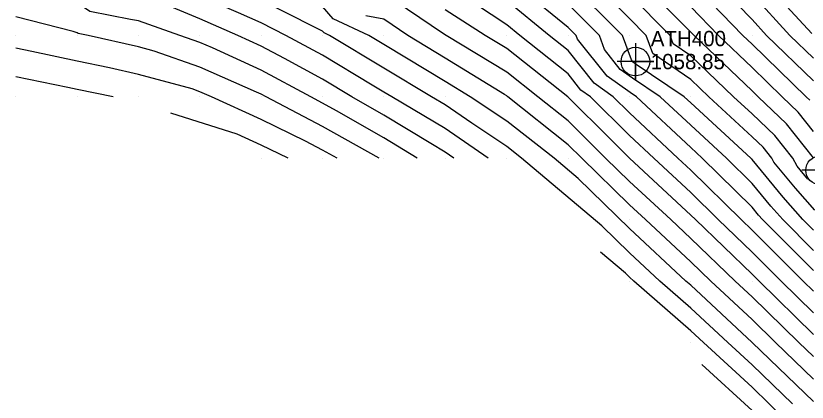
# Model space of a CAD drawing. Extents: x 1213164 to 1213550, y 766120 to 766870.
# Drawn here: x 1213170 to 1213299, y 766240.3 to 766303.2 of the extents above; entities that cross this region are included whole.
import ezdxf

# ---------------------------------------------------------------- set-up
doc = ezdxf.new("R2010")
doc.units = 0
for name, color, linetype in [('Default', 7, 'Continuous'), ('Exist DTM QL2 LIDAR Elevation Point', 7, 'Continuous'), ('Exist DTM Regular Point CELL', 7, 'Continuous'), ('Exist DTM Regular Point Cogo Elevation', 7, 'Continuous'), ('Exist DTM Regular Point Cogo Number', 7, 'Continuous')]:
    doc.layers.add(name, color=color, linetype=linetype)

msp = doc.modelspace()

# ---------------------------------------------------------------- linework, layer by layer
at = {"layer": 'Default'}
for points in [[(1213246.98, 766280), (1213240, 766284.82), (1213231.27, 766290), (1213230, 766290.76), (1213228.08, 766291.92), (1213220, 766296.78), (1213214.03, 766300), (1213210, 766302.06), (1213206.31, 766303.69), (1213200, 766306.44), (1213191.38, 766310), (1213190, 766310.57), (1213185.81, 766311.07), (1213184.05, 766311.81), (1213180, 766314.05), (1213174.54, 766315.46), (1213170, 766316.63)], [(1213241.4, 766280), (1213240, 766280.97), (1213237.62, 766282.38), (1213230, 766287.01), (1213224.78, 766290), (1213220, 766292.88), (1213213.77, 766296.23), (1213210, 766298.26), (1213206.17, 766300), (1213200, 766302.69), (1213195.42, 766304.58), (1213190, 766306.51), (1213186.46, 766307), (1213184, 766307.5), (1213180.32, 766309.98), (1213180, 766310.15), (1213179.79, 766310.21), (1213170, 766312.74)], [(1213300.21, 766271.55), (1213297.07, 766275.13), (1213293.55, 766279.37), (1213293.22, 766280), (1213291.8, 766281.8), (1213290, 766283.51), (1213282.95, 766290), (1213280, 766292.81), (1213273.8, 766297.08), (1213272.75, 766300), (1213270, 766302.77), (1213262.74, 766310)], [(1213300, 766280.07), (1213295.61, 766285.61), (1213291, 766290), (1213290, 766290.97), (1213280.53, 766300), (1213280, 766300.55), (1213270.63, 766310)], [(1213300, 766292.58), (1213292.36, 766300), (1213290, 766302.59), (1213282.84, 766310)], [(1213299.71, 766300.29), (1213290.8, 766310)], [(1213235.43, 766280), (1213230, 766283.3), (1213222.29, 766287.71), (1213220, 766288.99), (1213218.07, 766290), (1213210, 766294.34), (1213202.04, 766297.96), (1213200, 766298.86), (1213196.73, 766300), (1213190, 766302.4), (1213188.69, 766302.58), (1213182.08, 766303.91), (1213180, 766305.32), (1213172.13, 766307.87), (1213170, 766308.4)], [(1213300, 766268.28), (1213298.28, 766270), (1213295.06, 766273.67), (1213290, 766279.77), (1213289.77, 766280), (1213280, 766289.02), (1213278.95, 766290), (1213270.92, 766295.39), (1213270.66, 766295.58), (1213270.32, 766296), (1213268.89, 766300), (1213260, 766308.85)], [(1213299.43, 766289.43), (1213298.82, 766290), (1213290, 766298.56), (1213288.49, 766300), (1213280, 766308.77)], [(1213300, 766261.72), (1213291.7, 766270), (1213291.04, 766270.75), (1213290, 766272.01), (1213281.87, 766280), (1213280, 766281.73), (1213271.13, 766290), (1213270.12, 766290.68), (1213266.38, 766293.34), (1213261.53, 766299.41), (1213261.32, 766300), (1213260, 766301.31), (1213252.81, 766307.19)], [(1213300, 766247.71), (1213297.62, 766250), (1213290, 766257.45), (1213287.26, 766260), (1213280, 766266.94), (1213276.73, 766270), (1213270, 766276.23), (1213266.13, 766280), (1213260, 766286.08), (1213255.06, 766290), (1213250, 766294.02), (1213240.14, 766300), (1213240, 766300.09), (1213239.72, 766300.28), (1213230, 766306.89)], [(1213299.08, 766276.58), (1213297.32, 766278.7), (1213296.63, 766280), (1213293.7, 766283.7), (1213290, 766287.23), (1213286.99, 766290), (1213280, 766296.66), (1213277.12, 766298.64), (1213276.63, 766300), (1213270, 766306.69)], [(1213300, 766296.28), (1213296.17, 766300), (1213290, 766306.77)], [(1213296.59, 766240), (1213290, 766246.35), (1213286.02, 766250), (1213280, 766255.61), (1213274.96, 766260), (1213270, 766264.62), (1213265.5, 766269), (1213252.43, 766280), (1213250, 766281.89), (1213244.3, 766285.7), (1213240, 766288.67), (1213237.75, 766290), (1213230, 766294.64), (1213221.13, 766300), (1213220.26, 766300.4), (1213220, 766300.71), (1213218.66, 766301.34), (1213210, 766305.77)], [(1213300, 766240.37), (1213290.02, 766249.98), (1213290, 766250), (1213290, 766250), (1213280, 766259.31), (1213279.21, 766260), (1213270, 766268.58), (1213261.65, 766276.7), (1213257.73, 766280), (1213250, 766286.03), (1213244.05, 766290), (1213240, 766292.48), (1213233.68, 766296.32), (1213230, 766298.52), (1213227.56, 766300), (1213221.74, 766302.68), (1213220, 766304.72)], [(1213300, 766254.83), (1213294.72, 766260), (1213290, 766264.7), (1213284.47, 766270), (1213280, 766274.4), (1213273.97, 766280), (1213270, 766283.7), (1213263.66, 766290), (1213262.11, 766291.1), (1213260, 766293.74), (1213252.15, 766300), (1213250, 766301.75), (1213244.92, 766305.08)], [(1213300, 766258.34), (1213298.3, 766260), (1213290, 766268.27), (1213288.2, 766270), (1213280, 766278.07), (1213277.92, 766280), (1213270, 766287.38), (1213267.37, 766290), (1213264.25, 766292.22), (1213260, 766297.53), (1213256.9, 766300), (1213250, 766305.61)], [(1213300, 766265), (1213294.99, 766270), (1213293.05, 766272.21), (1213290, 766275.89), (1213285.82, 766280), (1213280, 766285.37), (1213275.04, 766290), (1213270.52, 766293.04), (1213268.52, 766294.46), (1213265.92, 766297.7), (1213265.1, 766300), (1213260, 766305.08)], [(1213300, 766284.38), (1213297.52, 766287.52), (1213294.91, 766290), (1213290, 766294.77), (1213284.51, 766300), (1213280, 766304.66)], [(1213300, 766251.32), (1213291.14, 766260), (1213290, 766261.13), (1213280.75, 766270), (1213280, 766270.74), (1213270.02, 766280), (1213270, 766280.02), (1213266.8, 766283.2), (1213260, 766289.95), (1213259.94, 766290), (1213250, 766297.89), (1213246.51, 766300), (1213240, 766304.15)], [(1213229.24, 766280), (1213220, 766285.16), (1213210.78, 766290), (1213210, 766290.42), (1213209.23, 766290.77), (1213200, 766294.85), (1213192.56, 766297.44), (1213190, 766298.14), (1213181.78, 766300), (1213180.17, 766300.32), (1213180, 766300.44), (1213179.35, 766300.65), (1213170, 766303)], [(1213300, 766244.04), (1213293.81, 766250), (1213290, 766253.73), (1213283.26, 766260), (1213280, 766263.12), (1213272.63, 766270), (1213270, 766272.44), (1213262.23, 766280), (1213260, 766282.21), (1213250.19, 766290), (1213250, 766290.15), (1213249.63, 766290.37), (1213240, 766296.28), (1213233.88, 766300), (1213230, 766302.64), (1213227.07, 766303.19)], [(1213222.38, 766280), (1213220, 766281.33), (1213217.2, 766282.8), (1213210, 766286.29), (1213201.89, 766290), (1213200, 766290.84), (1213198.72, 766291.28), (1213190, 766293.66), (1213185.27, 766294.73), (1213180, 766295.81), (1213172.61, 766297.39), (1213170, 766297.91)], [(1213185.88, 766290), (1213180, 766291.21), (1213178.46, 766291.54), (1213170, 766293.24)], [(1213214.4, 766280), (1213210, 766282.13), (1213206.07, 766283.93), (1213195.28, 766287.36)], [(1213300, 766232.77), (1213292.8, 766240), (1213290, 766242.7), (1213282.05, 766250), (1213280, 766251.91), (1213270.71, 766260), (1213270, 766260.66), (1213269.35, 766261.29), (1213265.27, 766264.73)], [(1213339.53, 766160.47), (1213336.58, 766170), (1213334.5, 766175.5), (1213332.7, 766180), (1213330, 766185.46), (1213327.6, 766190), (1213325.22, 766194.78), (1213322.53, 766200), (1213320, 766204.47), (1213316.56, 766210), (1213310, 766217.58), (1213307.97, 766220), (1213300, 766228.84), (1213298.91, 766230), (1213290, 766238.95), (1213281.79, 766246.43)]]:
    msp.add_lwpolyline(points, dxfattribs=at)
at = {"layer": 'Exist DTM QL2 LIDAR Elevation Point'}
for p, q in [((1213170, 766300), (1213170, 766300)), ((1213180, 766300), (1213180, 766300)), ((1213190, 766300), (1213190, 766300)), ((1213200, 766300), (1213200, 766300)), ((1213210, 766300), (1213210, 766300)), ((1213220, 766300), (1213220, 766300)), ((1213230, 766300), (1213230, 766300)), ((1213240, 766300), (1213240, 766300)), ((1213250, 766300), (1213250, 766300)), ((1213260, 766300), (1213260, 766300)), ((1213270, 766300), (1213270, 766300)), ((1213280, 766300), (1213280, 766300)), ((1213290, 766300), (1213290, 766300)), ((1213170, 766290), (1213170, 766290)), ((1213180, 766290), (1213180, 766290)), ((1213190, 766290), (1213190, 766290)), ((1213200, 766290), (1213200, 766290)), ((1213210, 766290), (1213210, 766290)), ((1213220, 766290), (1213220, 766290)), ((1213230, 766290), (1213230, 766290)), ((1213240, 766290), (1213240, 766290)), ((1213250, 766290), (1213250, 766290)), ((1213260, 766290), (1213260, 766290)), ((1213270, 766290), (1213270, 766290)), ((1213280, 766290), (1213280, 766290)), ((1213290, 766290), (1213290, 766290)), ((1213210, 766280), (1213210, 766280)), ((1213220, 766280), (1213220, 766280)), ((1213230, 766280), (1213230, 766280)), ((1213240, 766280), (1213240, 766280)), ((1213250, 766280), (1213250, 766280)), ((1213260, 766280), (1213260, 766280)), ((1213270, 766280), (1213270, 766280)), ((1213280, 766280), (1213280, 766280)), ((1213290, 766280), (1213290, 766280)), ((1213270, 766270), (1213270, 766270)), ((1213280, 766270), (1213280, 766270)), ((1213290, 766270), (1213290, 766270)), ((1213270, 766260), (1213270, 766260)), ((1213280, 766260), (1213280, 766260)), ((1213290, 766260), (1213290, 766260)), ((1213280, 766250), (1213280, 766250)), ((1213290, 766250), (1213290, 766250))]:
    msp.add_line(p, q, dxfattribs=at)
at = {"layer": 'Exist DTM Regular Point CELL'}
for points in [[(1213270.98, 766298.74), (1213270.98, 766292.74), (1213270.98, 766295.74), (1213273.98, 766295.74), (1213267.98, 766295.74)], [(1213301.08, 766281.04), (1213301.08, 766275.04), (1213301.08, 766278.04), (1213304.08, 766278.04), (1213298.08, 766278.04)]]:
    msp.add_lwpolyline(points, dxfattribs=at)
for centre in [(1213270.98, 766295.74), (1213301.08, 766278.04)]:
    msp.add_circle(centre, 2.34, dxfattribs=at)

# ---------------------------------------------------------------- texts
at = {"layer": 'Exist DTM Regular Point Cogo Elevation'}
msp.add_text('1058.85', height=2.5, dxfattribs=at).set_placement((1213273.48, 766294.49))
at = {"layer": 'Exist DTM Regular Point Cogo Number'}
msp.add_text('ATH400', height=2.5, dxfattribs=at).set_placement((1213273.48, 766298.24))

doc.saveas('drawing.dxf')
